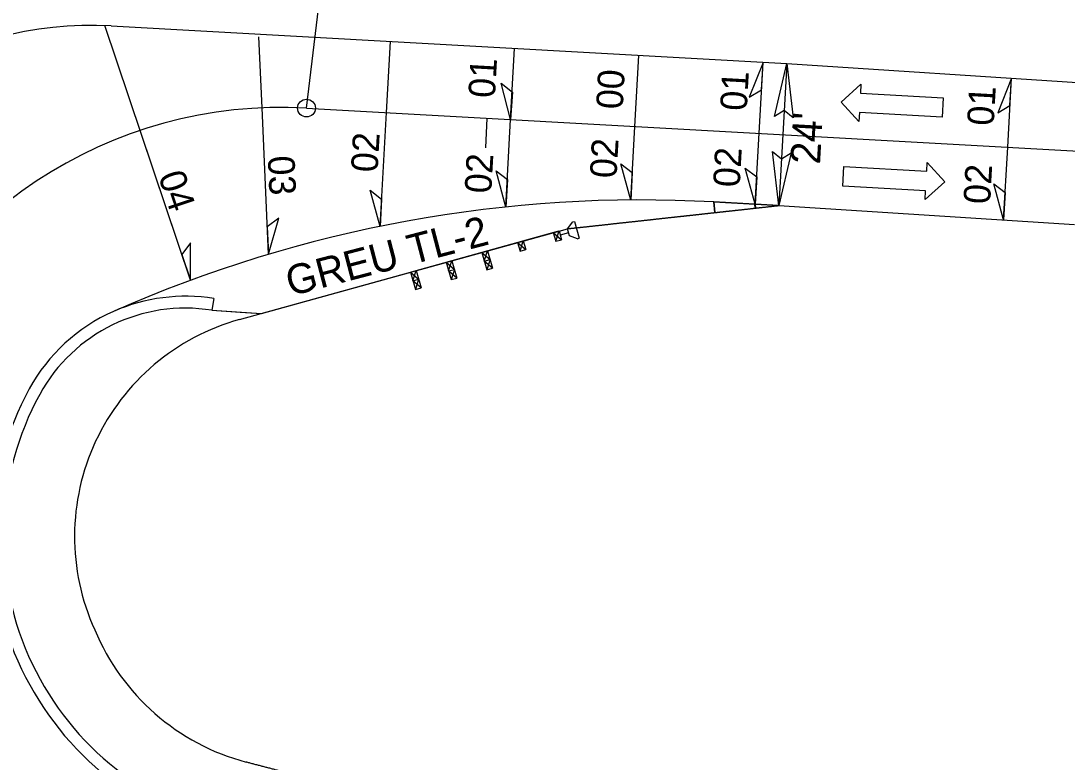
# Model space of a CAD drawing. Extents: x 1616561 to 1622460, y 896726 to 899651.
# Drawn here: x 1619580.2 to 1619756.7, y 898096.6 to 898221.7 of the extents above; entities that cross this region are included whole.
import ezdxf

# ---------------------------------------------------------------- set-up
doc = ezdxf.new("R2010")
doc.units = 0
for name, color, linetype in [('Old_Level_3', 7, 'Continuous'), ('Prop Dimension', 7, 'Continuous'), ('Prop Guardrail', 7, 'Continuous'), ('Prop Guardrail Anchor Unit CELL', 7, 'Continuous'), ('Prop Horizontal Alignment', 7, 'Continuous'), ('Prop Horizontal Alignment Tick Small', 7, 'Continuous'), ('Prop Lane Arrow CELL', 7, 'Continuous'), ('Prop North Arrow NAD83 for Plan Sheets CELL', 7, 'Continuous'), ('Prop Shade Light', 7, 'Continuous'), ('Prop Superelevation  Arrow CELL', 7, 'Continuous'), ('Prop Terminator CELL', 7, 'Continuous'), ('Sheet Cutting Line CELL', 7, 'Continuous'), ('Sheet North Arrow CELL', 7, 'Continuous'), ('Sheet Sticker Preliminary CELL', 7, 'Continuous')]:
    doc.layers.add(name, color=color, linetype=linetype)

msp = doc.modelspace()

# ---------------------------------------------------------------- linework, layer by layer
at = {"layer": 'Old_Level_3'}
for radius, start, end in [(808.75, 229.34838, 255.58792), (779.25, 244.13867, 256.29422), (791.25, 245.11013, 270)]:
    msp.add_arc((1619799.51, 898841.24), radius, start, end, dxfattribs=at)
at = {"layer": 'Prop Guardrail'}
msp.add_line((1619617.05, 898171.32), (1619645.9, 898179.32), dxfattribs=at)
for centre, radius, start, end in [((1619627.2, 898134.7), 38, 105.4983, 204.4603), ((1619628.01, 898133.66), 38.33, 202.5389, 255.0785)]:
    msp.add_arc(centre, radius, start, end, dxfattribs=at)
msp.add_spline([(1619656.5, 898087.47), (1619655.24, 898087.74), (1619654.6, 898087.88), (1619653.97, 898088.01), (1619653.34, 898088.15), (1619652.7, 898088.29), (1619652.07, 898088.42), (1619651.44, 898088.56), (1619650.8, 898088.7), (1619650.17, 898088.84), (1619649.54, 898088.98), (1619648.9, 898089.12), (1619648.27, 898089.26), (1619647.64, 898089.4), (1619647.01, 898089.54), (1619646.37, 898089.69), (1619645.74, 898089.83), (1619645.11, 898089.97), (1619644.48, 898090.12), (1619643.85, 898090.26), (1619643.22, 898090.41), (1619642.58, 898090.55), (1619641.95, 898090.7), (1619641.32, 898090.84), (1619640.69, 898090.99), (1619640.06, 898091.14), (1619639.43, 898091.29), (1619638.8, 898091.44), (1619638.17, 898091.58), (1619637.54, 898091.73), (1619636.91, 898091.88), (1619636.28, 898092.04), (1619635.65, 898092.19), (1619635.02, 898092.34), (1619634.39, 898092.49), (1619633.76, 898092.64), (1619633.13, 898092.8), (1619632.5, 898092.95), (1619631.87, 898093.11), (1619631.24, 898093.26), (1619630.62, 898093.42), (1619629.99, 898093.57), (1619629.36, 898093.73), (1619628.73, 898093.89), (1619628.1, 898094.04), (1619627.47, 898094.2), (1619626.85, 898094.36), (1619626.22, 898094.52), (1619625.59, 898094.68), (1619624.96, 898094.84), (1619624.34, 898095), (1619623.71, 898095.16), (1619623.08, 898095.32), (1619622.46, 898095.49), (1619621.83, 898095.65), (1619621.2, 898095.81), (1619620.58, 898095.98), (1619619.95, 898096.14), (1619619.32, 898096.31), (1619618.7, 898096.47), (1619618.14, 898096.62)], degree=3, dxfattribs=at)
at = {"layer": 'Prop Guardrail Anchor Unit CELL'}
for p, q in [((1619670.96, 898186.26), (1619672.38, 898186.65)), ((1619672.38, 898186.65), (1619673.28, 898187.79)), ((1619672.7, 898185.47), (1619672.38, 898186.65)), ((1619673.28, 898187.79), (1619673.58, 898187.87)), ((1619673.58, 898187.87), (1619674.36, 898185.04)), ((1619670.48, 898186.13), (1619646.38, 898179.45)), ((1619669.99, 898186), (1619670.96, 898186.27)), ((1619669.99, 898186), (1619670.4, 898184.54)), ((1619669.99, 898186), (1619671.36, 898184.8)), ((1619670.4, 898184.54), (1619670.96, 898186.27)), ((1619670.96, 898186.27), (1619671.36, 898184.8)), ((1619672.57, 898185.95), (1619671.15, 898185.56)), ((1619674.06, 898184.95), (1619672.7, 898185.47)), ((1619674.06, 898184.95), (1619674.36, 898185.04)), ((1619663.97, 898184.33), (1619664.93, 898184.6)), ((1619663.97, 898184.33), (1619664.38, 898182.87)), ((1619663.97, 898184.33), (1619665.34, 898183.13)), ((1619664.38, 898182.87), (1619664.93, 898184.6)), ((1619664.38, 898182.87), (1619665.34, 898183.13)), ((1619664.93, 898184.6), (1619665.34, 898183.13)), ((1619670.4, 898184.54), (1619671.36, 898184.8)), ((1619657.95, 898182.66), (1619658.91, 898182.93)), ((1619657.95, 898182.66), (1619658.76, 898179.73)), ((1619657.95, 898182.66), (1619659.32, 898181.46)), ((1619658.35, 898181.2), (1619658.91, 898182.93)), ((1619658.35, 898181.2), (1619659.32, 898181.46)), ((1619659.32, 898181.46), (1619658.76, 898179.73)), ((1619658.91, 898182.93), (1619659.72, 898180)), ((1619645.9, 898179.32), (1619646.87, 898179.59)), ((1619646.31, 898177.86), (1619646.87, 898179.59)), ((1619646.87, 898179.59), (1619647.68, 898176.66)), ((1619651.93, 898180.99), (1619652.89, 898181.26)), ((1619651.93, 898180.99), (1619652.74, 898178.06)), ((1619651.93, 898180.99), (1619653.29, 898179.79)), ((1619652.33, 898179.53), (1619652.89, 898181.26)), ((1619652.33, 898179.53), (1619653.29, 898179.79)), ((1619653.29, 898179.79), (1619652.74, 898178.06)), ((1619652.89, 898181.26), (1619653.7, 898178.33)), ((1619659.72, 898180), (1619658.35, 898181.2)), ((1619658.76, 898179.73), (1619659.72, 898180)), ((1619645.9, 898179.32), (1619646.71, 898176.39)), ((1619645.9, 898179.32), (1619647.27, 898178.12)), ((1619646.31, 898177.86), (1619647.27, 898178.12)), ((1619647.68, 898176.66), (1619646.31, 898177.86)), ((1619647.27, 898178.12), (1619646.71, 898176.39)), ((1619653.7, 898178.33), (1619652.33, 898179.53)), ((1619652.74, 898178.06), (1619653.7, 898178.33)), ((1619646.71, 898176.39), (1619647.68, 898176.66))]:
    msp.add_line(p, q, dxfattribs=at)
at = {"layer": 'Prop Horizontal Alignment'}
for p, q in [((1619620.76, 898172.35), (1619672.38, 898186.65)), ((1619612.71, 898174.86), (1619612.39, 898172.88)), ((1619612.39, 898172.88), (1619620.76, 898172.35))]:
    msp.add_line(p, q, dxfattribs=at)
msp.add_arc((1619607.9, 898145.25), 30, 80.7656, 113.8787, dxfattribs=at)
msp.add_open_spline([(1619672.38, 898186.65), (1619672.56, 898186.67), (1619672.74, 898186.69), (1619672.93, 898186.71), (1619673.11, 898186.73), (1619673.3, 898186.75), (1619673.48, 898186.77), (1619673.67, 898186.79), (1619673.85, 898186.81), (1619674.03, 898186.83), (1619674.22, 898186.85), (1619674.4, 898186.87), (1619674.59, 898186.89), (1619674.77, 898186.91), (1619674.95, 898186.93), (1619675.14, 898186.95), (1619675.32, 898186.97), (1619675.51, 898186.99), (1619675.69, 898187.01), (1619675.88, 898187.03), (1619676.06, 898187.05), (1619676.24, 898187.07), (1619676.43, 898187.09), (1619676.61, 898187.11), (1619676.8, 898187.13), (1619676.98, 898187.15), (1619677.16, 898187.17), (1619677.35, 898187.19), (1619677.53, 898187.21), (1619677.72, 898187.23), (1619677.9, 898187.25), (1619678.09, 898187.27), (1619678.27, 898187.29), (1619678.45, 898187.31), (1619678.64, 898187.33), (1619678.82, 898187.35), (1619679.01, 898187.37), (1619679.19, 898187.39), (1619679.38, 898187.41), (1619679.56, 898187.44), (1619679.74, 898187.46), (1619679.93, 898187.48), (1619680.11, 898187.5), (1619680.3, 898187.52), (1619680.48, 898187.54), (1619680.66, 898187.56), (1619680.85, 898187.58), (1619681.03, 898187.6), (1619681.22, 898187.62), (1619681.4, 898187.64), (1619681.59, 898187.66), (1619681.77, 898187.68), (1619681.95, 898187.7), (1619682.14, 898187.72), (1619682.32, 898187.74), (1619682.51, 898187.76), (1619682.69, 898187.78), (1619682.88, 898187.8), (1619683.06, 898187.82), (1619683.24, 898187.84), (1619683.43, 898187.86), (1619683.61, 898187.88), (1619683.8, 898187.9), (1619683.98, 898187.92), (1619684.16, 898187.94), (1619684.35, 898187.96), (1619684.53, 898187.98), (1619684.72, 898188), (1619684.9, 898188.02), (1619685.09, 898188.04), (1619685.27, 898188.06), (1619685.45, 898188.08), (1619685.64, 898188.1), (1619685.82, 898188.12), (1619686.01, 898188.14), (1619686.19, 898188.16), (1619686.38, 898188.18), (1619686.56, 898188.2), (1619686.74, 898188.22), (1619686.93, 898188.24), (1619687.11, 898188.26), (1619687.3, 898188.28), (1619687.48, 898188.31), (1619687.66, 898188.33), (1619687.85, 898188.35), (1619688.03, 898188.37), (1619688.22, 898188.39), (1619688.4, 898188.41), (1619688.59, 898188.43), (1619688.77, 898188.45), (1619688.95, 898188.47), (1619689.14, 898188.49), (1619689.32, 898188.51), (1619689.51, 898188.53), (1619689.69, 898188.55), (1619689.88, 898188.57), (1619690.06, 898188.59), (1619690.24, 898188.61), (1619690.43, 898188.63), (1619690.61, 898188.65), (1619690.8, 898188.67), (1619690.98, 898188.69), (1619691.16, 898188.71), (1619691.35, 898188.73), (1619691.53, 898188.75), (1619691.72, 898188.77), (1619691.9, 898188.79), (1619692.09, 898188.81), (1619692.27, 898188.83), (1619692.45, 898188.85), (1619692.64, 898188.87), (1619692.82, 898188.89), (1619693.01, 898188.91), (1619693.19, 898188.93), (1619693.38, 898188.95), (1619693.56, 898188.97), (1619693.74, 898188.99), (1619693.93, 898189.01), (1619694.11, 898189.03), (1619694.3, 898189.05), (1619694.48, 898189.07), (1619694.66, 898189.09), (1619694.85, 898189.11), (1619695.03, 898189.13), (1619695.22, 898189.15), (1619695.4, 898189.17), (1619695.59, 898189.2), (1619695.77, 898189.22), (1619695.95, 898189.24), (1619696.14, 898189.26), (1619696.32, 898189.28), (1619696.51, 898189.3), (1619696.69, 898189.32), (1619696.88, 898189.34), (1619697.06, 898189.36), (1619697.24, 898189.38), (1619697.43, 898189.4), (1619697.61, 898189.42), (1619697.8, 898189.44), (1619697.98, 898189.46), (1619698.16, 898189.48), (1619698.35, 898189.5), (1619698.53, 898189.52), (1619698.72, 898189.54), (1619698.9, 898189.56), (1619699.09, 898189.58), (1619699.27, 898189.6), (1619699.45, 898189.62), (1619699.64, 898189.64), (1619699.82, 898189.66), (1619700.01, 898189.68), (1619700.19, 898189.7), (1619700.38, 898189.72), (1619700.56, 898189.74), (1619700.74, 898189.76), (1619700.93, 898189.78), (1619701.11, 898189.8), (1619701.3, 898189.82), (1619701.48, 898189.84), (1619701.66, 898189.86), (1619701.85, 898189.88), (1619702.03, 898189.9), (1619702.22, 898189.92), (1619702.4, 898189.94), (1619702.59, 898189.96), (1619702.77, 898189.98), (1619702.95, 898190), (1619703.14, 898190.02), (1619703.32, 898190.04), (1619703.51, 898190.07), (1619703.69, 898190.09), (1619703.87, 898190.11), (1619704.06, 898190.13), (1619704.24, 898190.15), (1619704.43, 898190.17), (1619704.61, 898190.19), (1619704.8, 898190.21), (1619704.98, 898190.23), (1619705.16, 898190.25), (1619705.35, 898190.27), (1619705.53, 898190.29), (1619705.72, 898190.31), (1619705.9, 898190.33), (1619706.09, 898190.35), (1619706.27, 898190.37), (1619706.45, 898190.39), (1619706.64, 898190.41), (1619706.82, 898190.43), (1619707.01, 898190.45), (1619707.19, 898190.47), (1619707.37, 898190.49), (1619707.56, 898190.51), (1619707.74, 898190.53), (1619707.83, 898190.54), (1619707.92, 898190.55), (1619708.05, 898190.55)], degree=3, dxfattribs=at)
at = {"layer": 'Prop Horizontal Alignment Tick Small'}
msp.add_line((1619612.71, 898174.86), (1619612.39, 898172.88), dxfattribs=at)
for centre, radius, start, end in [((1619607.9, 898145.25), 28, 80.7656, 151.351), ((1619627.2, 898134.7), 50, 151.351, 256.2942)]:
    msp.add_arc(centre, radius, start, end, dxfattribs=at)
at = {"layer": 'Prop Lane Arrow CELL'}
for p, q in [((1619718.58, 898208.03), (1619721.9, 898211.04)), ((1619721.9, 898211.04), (1619721.82, 898209.55)), ((1619721.55, 898204.75), (1619718.58, 898208.03)), ((1619721.82, 898209.55), (1619735.8, 898208.77)), ((1619735.8, 898208.77), (1619735.61, 898205.47)), ((1619721.63, 898206.25), (1619721.55, 898204.75)), ((1619735.61, 898205.47), (1619721.63, 898206.25)), ((1619733, 898196.35), (1619733.08, 898197.85)), ((1619733.08, 898197.85), (1619736.05, 898194.58)), ((1619718.83, 898193.84), (1619719.02, 898197.13)), ((1619719.02, 898197.13), (1619733, 898196.35)), ((1619732.81, 898193.06), (1619718.83, 898193.84)), ((1619736.05, 898194.58), (1619732.73, 898191.56)), ((1619732.73, 898191.56), (1619732.81, 898193.06))]:
    msp.add_line(p, q, dxfattribs=at)
at = {"layer": 'Prop North Arrow NAD83 for Plan Sheets CELL'}
for p, q in [((1619621.94, 898182.34), (1619620.84, 898207.07)), ((1619640.75, 898187.05), (1619641.82, 898206.27)), ((1619608.76, 898177.95), (1619600.27, 898203.23))]:
    msp.add_line(p, q, dxfattribs=at)
for points in [[(1619705.39, 898214.74), (1619703.06, 898208.86), (1619705.13, 898210.12)], [(1619747.31, 898212.07), (1619744.98, 898206.19), (1619747.05, 898207.45)], [(1619662.79, 898205.1), (1619661.17, 898211.21), (1619663.08, 898209.72)], [(1619683.06, 898191.5), (1619681.4, 898197.6), (1619683.32, 898196.12)], [(1619661.96, 898190.32), (1619660.34, 898196.43), (1619662.25, 898194.94)], [(1619704.05, 898190.78), (1619702.39, 898196.88), (1619704.31, 898195.4)], [(1619745.97, 898188.15), (1619744.31, 898194.25), (1619746.23, 898192.77)], [(1619640.75, 898187.05), (1619639.08, 898193.15), (1619641, 898191.67)], [(1619621.94, 898182.34), (1619623.67, 898188.42), (1619621.73, 898186.96)], [(1619608.76, 898177.95), (1619608.75, 898184.27), (1619607.29, 898182.33)]]:
    msp.add_lwpolyline(points, close=True, dxfattribs=at)
at = {"layer": 'Prop Shade Light'}
for p, q in [((1619703.96, 898190.78), (1619697.07, 898191.17)), ((1619697.07, 898191.17), (1619697.27, 898189.38)), ((1619704.12, 898190.13), (1619703.96, 898190.78)), ((1619703.96, 898190.78), (1619704.12, 898190.13)), ((1619704.05, 898190.78), (1619703.96, 898190.78)), ((1619708.05, 898190.55), (1619704.05, 898190.78)), ((1619704.05, 898190.78), (1619704.05, 898190.78)), ((1619704.05, 898190.78), (1619704.12, 898190.13)), ((1619645.9, 898179.31), (1619672.38, 898186.65)), ((1619620.76, 898172.35), (1619645.9, 898179.32))]:
    msp.add_line(p, q, dxfattribs=at)
for points in [[(1619697.27, 898189.38), (1619697.07, 898191.17)], [(1619704.12, 898190.13), (1619704.05, 898190.78)], [(1619645.9, 898179.32), (1619645.9, 898179.31)], [(1619612.71, 898174.86), (1619612.39, 898172.88)], [(1619612.39, 898172.88), (1619617.13, 898172.58), (1619620.76, 898172.35)]]:
    msp.add_lwpolyline(points, dxfattribs=at)
for centre, radius, start in [((1619684.81, 897971.51), 220, 86.8045), ((1619607.9, 898145.25), 30, 80.7656)]:
    msp.add_arc(centre, radius, start, 113.8787, dxfattribs=at)
for points in [[(1619704.12, 898190.13), (1619704.23, 898190.14), (1619704.33, 898190.16), (1619704.43, 898190.17), (1619704.61, 898190.19), (1619704.8, 898190.21), (1619704.98, 898190.23), (1619705.16, 898190.25), (1619705.35, 898190.27), (1619705.53, 898190.29), (1619705.72, 898190.31), (1619705.9, 898190.33), (1619706.09, 898190.35), (1619706.27, 898190.37), (1619706.45, 898190.39), (1619706.64, 898190.41), (1619706.82, 898190.43), (1619707.01, 898190.45), (1619707.19, 898190.47), (1619707.37, 898190.49), (1619707.56, 898190.51), (1619707.74, 898190.53), (1619707.83, 898190.54), (1619707.92, 898190.55), (1619708.05, 898190.55)], [(1619672.38, 898186.65), (1619672.56, 898186.67), (1619672.74, 898186.69), (1619672.93, 898186.71), (1619673.11, 898186.73), (1619673.3, 898186.75), (1619673.48, 898186.77), (1619673.67, 898186.79), (1619673.85, 898186.81), (1619674.03, 898186.83), (1619674.22, 898186.85), (1619674.4, 898186.87), (1619674.59, 898186.89), (1619674.77, 898186.91), (1619674.95, 898186.93), (1619675.14, 898186.95), (1619675.32, 898186.97), (1619675.51, 898186.99), (1619675.69, 898187.01), (1619675.88, 898187.03), (1619676.06, 898187.05), (1619676.24, 898187.07), (1619676.43, 898187.09), (1619676.61, 898187.11), (1619676.8, 898187.13), (1619676.98, 898187.15), (1619677.16, 898187.17), (1619677.35, 898187.19), (1619677.53, 898187.21), (1619677.72, 898187.23), (1619677.9, 898187.25), (1619678.09, 898187.27), (1619678.27, 898187.29), (1619678.45, 898187.31), (1619678.64, 898187.33), (1619678.82, 898187.35), (1619679.01, 898187.37), (1619679.19, 898187.39), (1619679.38, 898187.41), (1619679.56, 898187.44), (1619679.74, 898187.46), (1619679.93, 898187.48), (1619680.11, 898187.5), (1619680.3, 898187.52), (1619680.48, 898187.54), (1619680.66, 898187.56), (1619680.85, 898187.58), (1619681.03, 898187.6), (1619681.22, 898187.62), (1619681.4, 898187.64), (1619681.59, 898187.66), (1619681.77, 898187.68), (1619681.95, 898187.7), (1619682.14, 898187.72), (1619682.32, 898187.74), (1619682.51, 898187.76), (1619682.69, 898187.78), (1619682.88, 898187.8), (1619683.06, 898187.82), (1619683.24, 898187.84), (1619683.43, 898187.86), (1619683.61, 898187.88), (1619683.8, 898187.9), (1619683.98, 898187.92), (1619684.16, 898187.94), (1619684.35, 898187.96), (1619684.53, 898187.98), (1619684.72, 898188), (1619684.9, 898188.02), (1619685.09, 898188.04), (1619685.27, 898188.06), (1619685.45, 898188.08), (1619685.64, 898188.1), (1619685.82, 898188.12), (1619686.01, 898188.14), (1619686.19, 898188.16), (1619686.38, 898188.18), (1619686.56, 898188.2), (1619686.74, 898188.22), (1619686.93, 898188.24), (1619687.11, 898188.26), (1619687.3, 898188.28), (1619687.48, 898188.31), (1619687.66, 898188.33), (1619687.85, 898188.35), (1619688.03, 898188.37), (1619688.22, 898188.39), (1619688.4, 898188.41), (1619688.59, 898188.43), (1619688.77, 898188.45), (1619688.95, 898188.47), (1619689.14, 898188.49), (1619689.32, 898188.51), (1619689.51, 898188.53), (1619689.69, 898188.55), (1619689.88, 898188.57), (1619690.06, 898188.59), (1619690.1, 898188.59), (1619690.15, 898188.6), (1619690.2, 898188.6)], [(1619690.2, 898188.6), (1619690.33, 898188.62), (1619690.47, 898188.63), (1619690.61, 898188.65), (1619690.8, 898188.67), (1619690.98, 898188.69), (1619691.16, 898188.71), (1619691.35, 898188.73), (1619691.53, 898188.75), (1619691.72, 898188.77), (1619691.9, 898188.79), (1619692.09, 898188.81), (1619692.27, 898188.83), (1619692.45, 898188.85), (1619692.64, 898188.87), (1619692.82, 898188.89), (1619693.01, 898188.91), (1619693.19, 898188.93), (1619693.38, 898188.95), (1619693.56, 898188.97), (1619693.74, 898188.99), (1619693.93, 898189.01), (1619694.11, 898189.03), (1619694.3, 898189.05), (1619694.48, 898189.07), (1619694.66, 898189.09), (1619694.85, 898189.11), (1619695.03, 898189.13), (1619695.22, 898189.15), (1619695.4, 898189.17), (1619695.59, 898189.2), (1619695.77, 898189.22), (1619695.95, 898189.24), (1619696.14, 898189.26), (1619696.32, 898189.28), (1619696.51, 898189.3), (1619696.69, 898189.32), (1619696.88, 898189.34), (1619697.06, 898189.36), (1619697.24, 898189.38), (1619697.25, 898189.38), (1619697.26, 898189.38), (1619697.27, 898189.38)], [(1619697.27, 898189.38), (1619697.44, 898189.4), (1619697.62, 898189.42), (1619697.8, 898189.44), (1619697.98, 898189.46), (1619698.16, 898189.48), (1619698.35, 898189.5), (1619698.53, 898189.52), (1619698.72, 898189.54), (1619698.9, 898189.56), (1619699.09, 898189.58), (1619699.27, 898189.6), (1619699.45, 898189.62), (1619699.64, 898189.64), (1619699.82, 898189.66), (1619700.01, 898189.68), (1619700.19, 898189.7), (1619700.38, 898189.72), (1619700.56, 898189.74), (1619700.74, 898189.76), (1619700.93, 898189.78), (1619701.11, 898189.8), (1619701.3, 898189.82), (1619701.48, 898189.84), (1619701.66, 898189.86), (1619701.85, 898189.88), (1619702.03, 898189.9), (1619702.22, 898189.92), (1619702.4, 898189.94), (1619702.59, 898189.96), (1619702.77, 898189.98), (1619702.95, 898190), (1619703.14, 898190.02), (1619703.32, 898190.04), (1619703.51, 898190.07), (1619703.69, 898190.09), (1619703.87, 898190.11), (1619703.96, 898190.11), (1619704.04, 898190.12), (1619704.12, 898190.13)]]:
    msp.add_open_spline(points, degree=3, dxfattribs=at)
at = {"layer": 'Prop Superelevation  Arrow CELL'}
msp.add_line((1619658.79, 898205.32), (1619658.52, 898200.33), dxfattribs=at)
at = {"layer": 'Prop Terminator CELL'}
for p, q in [((1619595.36, 898220.88), (1619709.38, 898214.52)), ((1619709.38, 898214.52), (1619759.28, 898211.29)), ((1619697.07, 898191.17), (1619708.05, 898190.55)), ((1619708.05, 898190.55), (1619757.95, 898187.36))]:
    msp.add_line(p, q, dxfattribs=at)
for points in [[(1619707.34, 898205.62), (1619709.38, 898214.52), (1619710.48, 898205.39), (1619708.94, 898206.63)], [(1619710.1, 898199.45), (1619708.05, 898190.55), (1619706.95, 898199.68), (1619708.49, 898198.44)]]:
    msp.add_lwpolyline(points, close=True, dxfattribs=at)
for centre, radius, start, end in [((1619592.02, 898160.98), 60, 86.8045, 160.2164), ((1619684.81, 897971.51), 220, 86.8045, 113.8787), ((1619607.9, 898145.25), 30, 113.8787, 151.351), ((1619627.2, 898134.7), 52, 151.351, 256.2942)]:
    msp.add_arc(centre, radius, start, end, dxfattribs=at)
at = {"layer": 'Sheet Cutting Line CELL'}
msp.add_line((1619628.34, 898207.02), (1619823.96, 898196.1), dxfattribs=at)
for centre, radius, start, end in [((1619799.51, 898841.24), 800, 229.34838, 270), ((1619624.16, 898132.14), 75, 86.8045, 160.2164)]:
    msp.add_arc(centre, radius, start, end, dxfattribs=at)
at = {"layer": 'Sheet North Arrow CELL'}
msp.add_line((1619628.34, 898207.02), (1619641.63, 898318.02), dxfattribs=at)
msp.add_circle((1619628.34, 898207.02), 1.5, dxfattribs=at)
at = {"layer": 'Sheet Sticker Preliminary CELL'}
for p, q in [((1619608.76, 898177.95), (1619594.32, 898220.94)), ((1619620.84, 898207.06), (1619620.31, 898219.06)), ((1619641.82, 898206.27), (1619642.49, 898218.25)), ((1619662.79, 898205.1), (1619663.46, 898217.08)), ((1619683.75, 898203.93), (1619684.42, 898215.91)), ((1619704.72, 898202.76), (1619705.39, 898214.74)), ((1619709.38, 898214.52), (1619708.05, 898190.55)), ((1619746.66, 898200.42), (1619747.31, 898212.07)), ((1619661.96, 898190.32), (1619662.79, 898205.1)), ((1619683.06, 898191.5), (1619683.75, 898203.93)), ((1619704.05, 898190.78), (1619704.72, 898202.76)), ((1619745.97, 898188.15), (1619746.66, 898200.42))]:
    msp.add_line(p, q, dxfattribs=at)

# ---------------------------------------------------------------- texts
at = {"layer": 'Prop Dimension'}
msp.add_text("24'", height=5, rotation=86.8045, dxfattribs=at).set_placement((1619714.99, 898197.44))
at = {"layer": 'Prop Guardrail Anchor Unit CELL'}
msp.add_text('GREU TL-2', height=5, rotation=14.6515, dxfattribs=at).set_placement((1619625.62, 898175.23))
at = {"layer": 'Sheet Sticker Preliminary CELL'}
for s, rotation, p in [('01', 86.8045, (1619660.13, 898208.65)), ('00', 86.8045, (1619681.69, 898206.74)), ('01', 86.8045, (1619702.62, 898206.48)), ('01', 86.8045, (1619744.29, 898203.96)), ('02', 86.8045, (1619640.33, 898196.1)), ('02', 86.8045, (1619680.64, 898195.1)), ('02', 86.8045, (1619659.51, 898192.54)), ('02', 86.8045, (1619701.43, 898193.58)), ('03', 272.5307, (1619621.81, 898198.9)), ('02', 86.8045, (1619743.68, 898190.73)), ('04', 288.5735, (1619603.28, 898195.57))]:
    msp.add_text(s, height=4.5, rotation=rotation, dxfattribs=at).set_placement(p)

doc.saveas('drawing.dxf')
